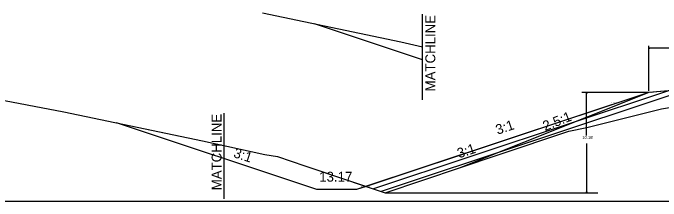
# Model space of a CAD drawing. Extents: x 2207892 to 2209721, y 61220 to 65449.
# Drawn here: x 2208021.8 to 2208087.2, y 63907.3 to 63926.3 of the extents above; entities that cross this region are included whole.
import ezdxf

# ---------------------------------------------------------------- set-up
doc = ezdxf.new("R2010")
doc.units = 0
for name, color, linetype in [('Exist DTM Breakline Cogo Comment', 7, 'Continuous'), ('Exist DTM Breakline Cogo Elevation', 7, 'Continuous'), ('Exist DTM Breakline Underwater Cogo Comment', 7, 'Continuous'), ('Exist DTM Ridgeline Cogo Comment', 7, 'Continuous'), ('Exist Hydro Stream or Body of Water Cogo Elevation', 7, 'Continuous'), ('Exist Roads EOP Other', 7, 'Continuous'), ('Exist Roads EOP Other Cogo Elevation', 7, 'Continuous'), ('Exist Roads EOP Other Cogo Number', 7, 'Continuous'), ('Exist Structure Minor Head and End Wall Cogo Point CELL', 7, 'Continuous')]:
    doc.layers.add(name, color=color, linetype=linetype)

msp = doc.modelspace()

# ---------------------------------------------------------------- linework, layer by layer
at = {"layer": 'Exist DTM Breakline Cogo Comment'}
for points in [[(2208077.94, 63914.387), (2208079.76, 63914.764), (2208087.292, 63916.634), (2208091.105, 63917.271), (2208095.317, 63917.898), (2208095.65, 63918.003), (2208090.43, 63917.69), (2208089.533, 63918.587), (2208085.994, 63918.304), (2208057.472, 63908.797), (2208059.415, 63908.147), (2208070.801, 63911.991)], [(2208056.523, 63908.48), (2208052.523, 63908.48), (2208032.284, 63915.227), (2208040.968, 63913.397), (2208047.247, 63912.026), (2208048.554, 63911.804), (2208051.283, 63910.888), (2208051.909, 63910.657), (2208057.472, 63908.797)]]:
    msp.add_lwpolyline(points, close=True, dxfattribs=at)
at = {"layer": 'Exist DTM Breakline Cogo Elevation'}
for p, q in [((2208063.174, 63917.536), (2208063.174, 63926.208)), ((2208063.174, 63921.597), (2208052.284, 63925.227)), ((2208043.174, 63907.536), (2208043.174, 63916.208))]:
    msp.add_line(p, q, dxfattribs=at)
msp.add_lwpolyline([(2208047.025, 63926.335), (2208060.968, 63923.397), (2208063.174, 63922.915)], dxfattribs=at)
at = {"layer": 'Exist Hydro Stream or Body of Water Cogo Elevation'}
for p, q in [((2208052.523, 63908.48), (2208032.284, 63915.227)), ((2208056.523, 63908.48), (2208052.523, 63908.48))]:
    msp.add_line(p, q, dxfattribs=at)
msp.add_lwpolyline([(2208091.994, 63918.784), (2208085.994, 63918.304), (2208056.523, 63908.48)], dxfattribs=at)
at = {"layer": 'Exist Roads EOP Other'}
for p, q in [((2208085.994, 63918.464), (2208085.994, 63923.014)), ((2208085.994, 63918.514), (2208085.994, 63922.807)), ((2208090.199, 63922.757), (2208085.994, 63922.757)), ((2208087.994, 63918.464), (2208058.231, 63908.543)), ((2208089.994, 63918.624), (2208058.99, 63908.289)), ((2208085.994, 63918.304), (2208067.019, 63910.714)), ((2208085.994, 63918.304), (2208079.244, 63918.304)), ((2208081.536, 63918.304), (2208079.674, 63918.304)), ((2208079.724, 63913.944), (2208079.724, 63918.304)), ((2208079.724, 63913.126), (2208079.724, 63908.147)), ((2208059.415, 63908.147), (2208080.873, 63908.147)), ((2208059.465, 63908.147), (2208079.774, 63908.147))]:
    msp.add_line(p, q, dxfattribs=at)
for points in [[(2208086.094, 63922.732), (2208085.994, 63922.757), (2208086.094, 63922.782)], [(2208079.699, 63918.204), (2208079.724, 63918.304), (2208079.749, 63918.204)], [(2208079.749, 63908.247), (2208079.724, 63908.147), (2208079.699, 63908.247)]]:
    msp.add_lwpolyline(points, dxfattribs=at)
at = {"layer": 'Exist Roads EOP Other Cogo Elevation'}
msp.add_lwpolyline([(2208019.533, 63917.733), (2208026.997, 63916.341), (2208040.968, 63913.397), (2208047.247, 63912.026), (2208048.554, 63911.804), (2208051.283, 63910.888), (2208051.909, 63910.657), (2208059.415, 63908.147), (2208070.801, 63911.991), (2208077.94, 63914.387), (2208079.76, 63914.764), (2208087.292, 63916.634)], dxfattribs=at)
at = {"layer": 'Exist Roads EOP Other Cogo Number'}
msp.add_line((2207918.174, 63907.31), (2208118.174, 63907.31), dxfattribs=at)

# ---------------------------------------------------------------- texts
at = {"layer": 'Exist DTM Breakline Cogo Elevation'}
for p in [(2208064.458, 63918.404), (2208042.89, 63908.404)]:
    msp.add_text('MATCHLINE', height=1, rotation=90, dxfattribs=at).set_placement(p)
at = {"layer": 'Exist DTM Breakline Underwater Cogo Comment'}
msp.add_text('3:1', height=1, rotation=341.56505, dxfattribs=at).set_placement((2208044.024, 63911.774))
msp.add_text('13.17', height=1, dxfattribs=at).set_placement((2208052.747, 63909.272))
at = {"layer": 'Exist DTM Ridgeline Cogo Comment'}
msp.add_text('3:1', height=1, rotation=18.43323, dxfattribs=at).set_placement((2208070.743, 63914.012))
at = {"layer": 'Exist Roads EOP Other'}
for s, rotation, p in [('2.5:1', 21.80141, (2208075.539, 63914.379)), ('3:1', 18.43495, (2208066.856, 63911.63))]:
    msp.add_text(s, height=1, rotation=rotation, dxfattribs=at).set_placement(p)
msp.add_text("10.16'", height=0.3, dxfattribs=at).set_placement((2208079.282, 63913.589))
at = {"layer": 'Exist Structure Minor Head and End Wall Cogo Point CELL'}
for s, p in [('LT_GS_OS_CTL', (2208085.462, 63918.254)), ('LT_Sub_OSS_DLT', (2208082.144, 63917.181)), ('LT_Slope_Fill', (2208056.997, 63908.747))]:
    msp.add_text(s, height=0.1, dxfattribs=at).set_placement(p)

doc.saveas('drawing.dxf')
